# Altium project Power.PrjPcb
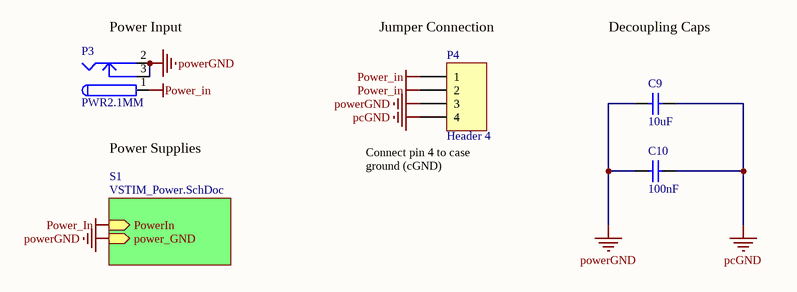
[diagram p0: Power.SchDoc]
2 sheets, 21 parts. Net scope: strictly hierarchical (ports join the sheet entries above them; power ports are local).
Board file: Power.PcbDoc
Sheets:
  Power.SchDoc
    S1 = VSTIM_Power.SchDoc

## Sheet Power.SchDoc
size A4

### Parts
C9  10uF  [C0805]
C10  Capacitance: 100nF  [CAPC2013X135X45ML10T25]  (hidden comment: GRM21BR71H104KA01L)
P3  PWR2.1MM  [POWER2.1MM]
P4  Header 4  [OSTVN04A150]

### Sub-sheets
S1 = VSTIM_Power.SchDoc: PowerIn (in), power_GND (in)

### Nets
pcGND: C9.1 C10.1 P4.4
Power_in: P3.1 P4.1 P4.2 ; sheet S1/PowerIn
powerGND: C9.2 C10.2 P3.2 P3.3 P4.3 ; sheet S1/power_GND  [project net EPAD]

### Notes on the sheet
- (near P3) Power Input
- (near P4) Jumper Connection
- Decoupling Caps
- (near P3) Power Supplies
- (near P4) Connect pin 4 to case ground (cGND)

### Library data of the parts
C9 = C2012X5R1E106K085AC: CAP 10UF; Manufacturer: Samsung Electro-Mechanics; Manufacturer Part Number: CL21A106KAYNNNE; Dielectric Material: Ceramic; Tolerance: 10%; Voltage Rating: 25V; Dielectric: X5R
C10 = CMP-2100-03644-1: Chip Capacitor, 0.1 uF, +/- 10%, 50 V, -55 to 125 degC, 0805 (2012 Metric), RoHS, Tape and Reel; Manufacturer: Murata; Voltage: 50V; Insulation Resistance: 10GR; Dielectric Material: Ceramic; Dielectric: X7R
P3 = PWR2.1MM: PJ-002AH; Manufacturer: CUI; Gender: Male; Shielding: Unshielded; Connector Type: Jack; Current Rating: 5A; Number of Conductors: 2; Voltage Rating: 24V; Insulation Resistance: 50MR
P4 = Header 4: Header, 4-Pin; Manufacturer: On Shore Technology Inc.; Detailed Description: 4 Position Wire to Board Terminal Block Horizontal with Board 0.100" (2.54mm) Through Hole; Pitch (Imperial): 100mil

## Sheet VSTIM_Power.SchDoc
size A4
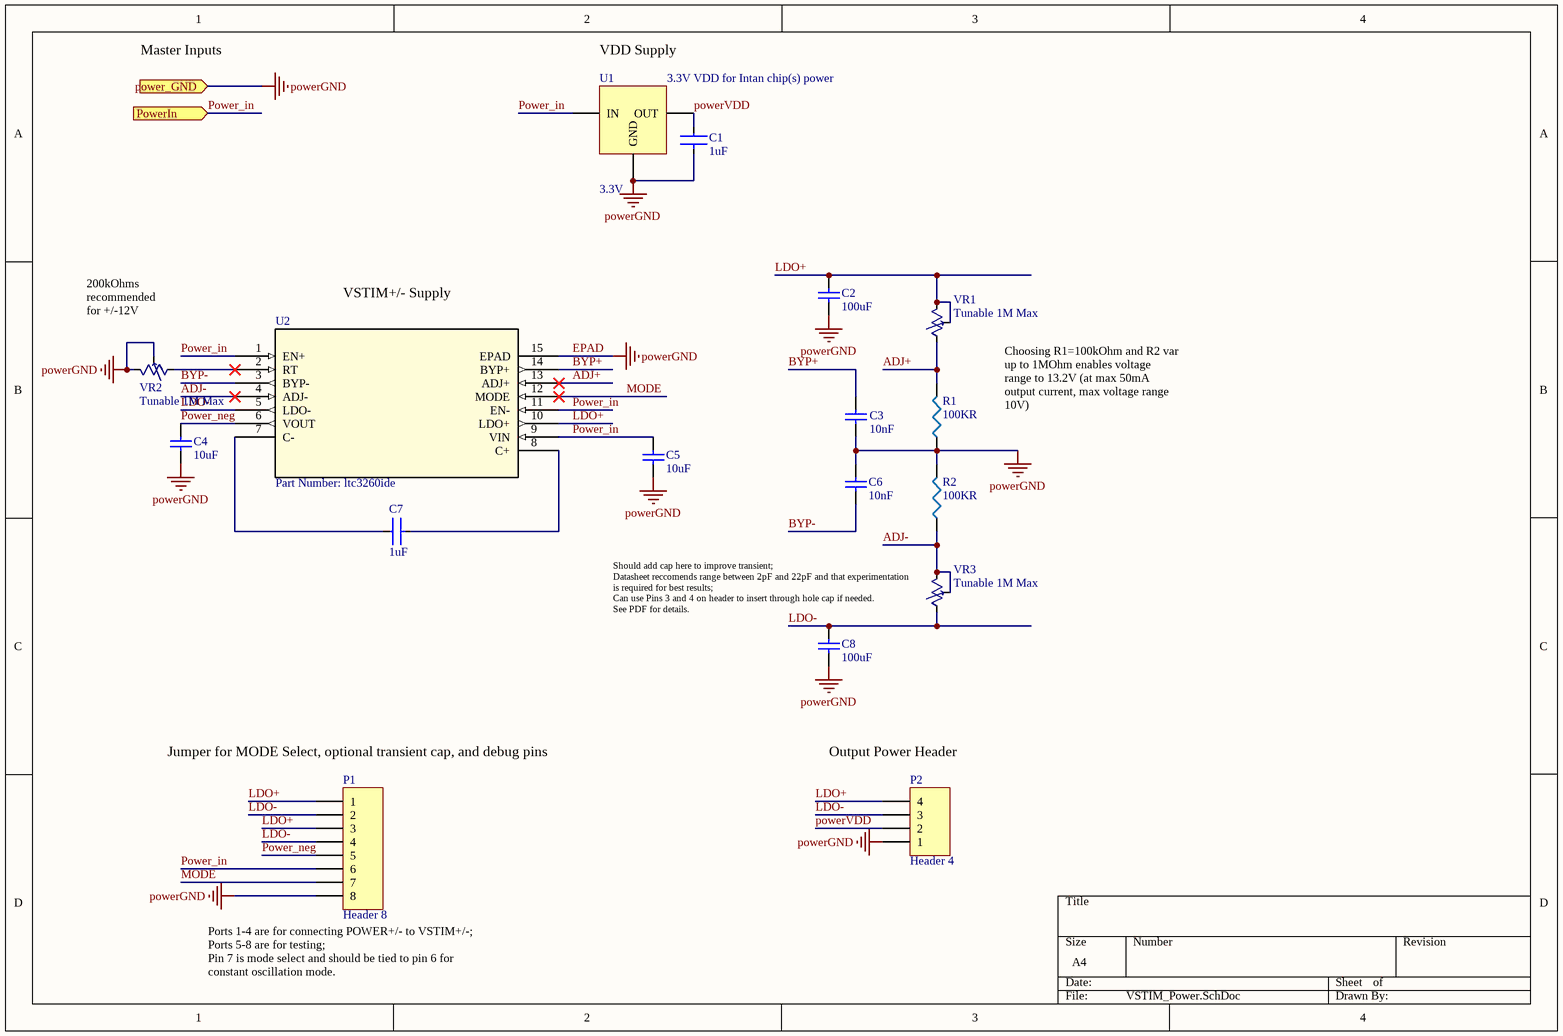
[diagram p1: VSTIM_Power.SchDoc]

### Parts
C1  Capacitance: 1uF  [FP-CC0805-0_85-MFG]  (hidden comment: CC0805KKX7R7BB105)
C2  100uF  [CAP_EEFK_D]
C3  Capacitance: 10nF  [CAPC2013X75X45LL10T25]  (hidden comment: CL21B103KBANNNC)
C4  10uF  [C0805]
C5  10uF  [C0805]
C6  Capacitance: 10nF  [CAPC2013X75X45LL10T25]  (hidden comment: CL21B103KBANNNC)
C7  Capacitance: 1uF  [FP-CC0805-0_85-MFG]  (hidden comment: CC0805KKX7R7BB105)
C8  100uF  [CAP_EEFK_D]
P1  Header 8  [TE_5-535541-6]
P2  Header 4  [OSTVN04A150]
R1  100KR  [R0805]
R2  100KR  [R0805]
U1  3.3V  [LM1085]
U2  Part Number: ltc3260ide  [DFN-14_DE]
VR1  Tunable 1M Max  [res_var_5turn]
VR2  Tunable 1M Max  [res_var_5turn]
VR3  Tunable 1M Max  [res_var_5turn]

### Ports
power_GND (in), PowerIn (in)

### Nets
EPAD: C1.1 C2.1 C3.1 C4.1 C5.1 C6.1 C8.1 P1.8 P2.1 R1.1 R2.2 U1.1(GND) U2.15(EPAD) VR2.1 VR2.2 ; port power_GND  [also labelled powerGND]
Power_in: C5.2 P1.6 U1.3(IN) U2.1(EN+) U2.9(VIN) U2.11(EN-) ; port PowerIn
ADJ+: R1.2 U2.13(ADJ+) VR1.3
ADJ-: R2.1 U2.4(ADJ-) VR3.1 VR3.2
BYP+: C3.2 U2.14(BYP+)
BYP-: C6.2 U2.3(BYP-)
LDO+: C2.2 P1.1 P1.3 P2.4 U2.10(LDO+) VR1.1 VR1.2
LDO-: C8.2 P1.2 P1.4 P2.3 U2.5(LDO-) VR3.3
MODE: P1.7 U2.12(MODE)
Power_neg: C4.2 P1.5 U2.6(VOUT)
powerVDD: C1.2 P2.2 U1.2(OUT)
NetC7_1: C7.1 U2.8(C+)
NetC7_2: C7.2 U2.7(C-)
NetU2_2: U2.2(RT) VR2.3

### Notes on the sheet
- Master Inputs
- VDD Supply
- (near U1) 3.3V VDD for Intan chip(s) power
- VSTIM+/- Supply
- (near VR2) 200kOhms recommended for +/-12V
- Choosing R1=100kOhm and R2 var up to 1MOhm enables voltage range to 13.2V (at max 50mA output current, max voltage range 10V)
- Should add cap here to improve transient;
  Datasheet reccomends range between 2pF and 22pF and that experimentation is required for best results;
  Can use Pins 3 and 4 on header to insert through hole cap if needed.
  See PDF for details.
- (near P1) Jumper for MODE Select, optional transient cap, and debug pins
- (near P2) Output Power Header
- (near P1) Ports 1-4 are for connecting POWER+/- to VSTIM+/-;
  Ports 5-8 are for testing;
  Pin 7 is mode select and should be tied to pin 6 for constant oscillation mode.

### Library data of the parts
C1 C7 = CMP-03422-000001-1: CAP CER 1UF 16V X7R 0805; Manufacturer: Yageo; Material: Ceramic; Tolerance: 0.1
C2 C8 = C2012X5R1E106K085AC: CAP ALUM 100UF 20% 35V SMD; Manufacturer: Panasonic Electronic Components; Manufacturer Part Number: EEE-FT1V101AP; Dielectric: Electrolytic Capacitor; Diam.: 6.3mm; Polarization: Polarized; ESR (Equivalent Series Resistance): 260mOhm @ 100kHz; Ripple Current @ Low Frequency: 195mA @ 120Hz; Ripple Current @ High Frequency: 300mA @ 100kHz
C3 C6 = CMP-2000-06105-1: Multilayer Ceramic Capacitor, 10 nF, 50 V, -55 to 125 degC, 2-Pin SMD, RoHS, Tape and Reel; Manufacturer: Samsung Electro-Mechanics; Tolerance (%): ±10%; Dielectric: X7R; Rated Voltage: 50V
C4 C5 = C2012X5R1E106K085AC: as C9 on sheet Power
P1 = Header 8: Header, 8-Pin; Manufacturer: TE Connectivity AMP Connectors; Manufacturer Part Number: 5-535541-6
P2 = Header 4: Header, 4-Pin; Manufacturer: On Shore Technology Inc.; Detailed Description: 4 Position Wire to Board Terminal Block Horizontal with Board 0.100" (2.54mm) Through Hole; Pitch (imperial): 100mil
R1 R2 = RES100: CRCW0805100KFKEA; Manufacturer: Vishay Dale; Tolerance: 1%; Temperature Coefficient: 100ppm/°C; Power Rating: 125mW; Voltage Rating: 200V
U1 = LM1085: LM1085ISX-3.3/NOPB; Manufacturer: TI National Semiconductor; Number of Outputs: 1; Min Input Voltage: 2.6V; Max Input Voltage: 27V; Max Output Current: 3A; Polarity: Positive; Quiescent Current: 10mA; Dropout Voltage: 1.3V; Min Current Limit: 3.2A
U2 = LTC3260IDE: IC REG CHARGE PUMP INV 14DFN; Manufacturer: Linear Technology/Analog Devices; Manufacturer Part Number: LTC3260EDE#TRPBF; Vendor: Linear Technology; Detailed Description: Charge Pump Switching Regulator IC Positive and Negative (Dual Rail) Fixed -Vin 2 Output 100mA 14-WFDFN Exposed Pad; Pricing1: Price Break  Unit Price  Extended Price  1  13.01000  $13.01  25  9.55440  $238.86  100  7.14360  $714.36  250  6.78644  $1,696.61  500  6.63338  $3,316.69 (CAD); Voltage - Input (Min): 4.5V; Voltage - Input (Max): 32V; Current - Output: 100mA; Frequency - Switching: 50kHz ~ 500kHz; Synchronous Rectifier: No; Output Configuration: Positive and Negative (Dual Rail)
VR1-VR3 = RES_VAR_5TURN: TRIMMER 1M OHM 0.25W J LEAD TOP; Manufacturer: Nidec Copal; Manufacturer Part Number: SM-42TW105; Resistance: 1MOhms; Tolerance: 10%; Number of Turns: 11; Max Power Dissipation: 250mW; Temperature Coefficient: 100ppm/°C

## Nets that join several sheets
EPAD: Power (5 pins), VSTIM_Power (15 pins)
Power_in: Power (P3.1 P4.1 P4.2), VSTIM_Power (6 pins)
